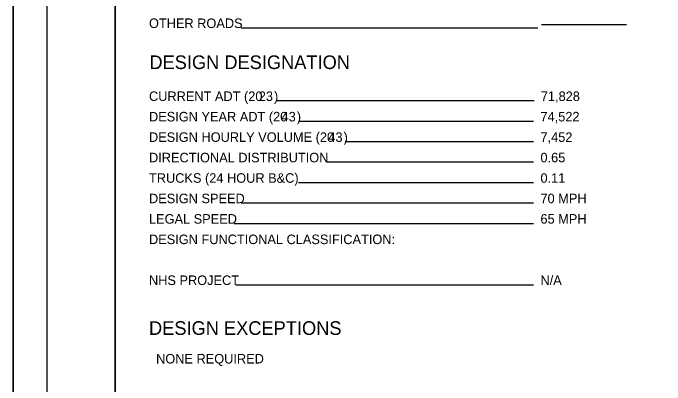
# Model space of a CAD drawing. Extents: x 0 to 44.3, y 0 to 22.
# Drawn here: x 0 to 9.56, y 5.64 to 11.1 of the extents above; entities that cross this region are included whole.
import ezdxf

# ---------------------------------------------------------------- set-up
doc = ezdxf.new("R2010")
doc.units = 0
for name, color, linetype in [('SH_Border', 7, 'Continuous'), ('SH_Cut_Line', 7, 'Continuous'), ('SH_Data', 7, 'Continuous'), ('SH_Text', 7, 'Continuous')]:
    doc.layers.add(name, color=color, linetype=linetype)

msp = doc.modelspace()

# ---------------------------------------------------------------- linework, layer by layer
at = {"layer": 'SH_Border'}
for points in [[(0.5, 21.5), (1.5, 21.5), (1.5, 0.5), (0.5, 0.5)], [(1.5, 21.5), (33.5, 21.5), (33.5, 0.5), (1.5, 0.5)]]:
    msp.add_lwpolyline(points, close=True, dxfattribs=at)
at = {"layer": 'SH_Cut_Line'}
for points in [[(0, 0), (34, 0), (34, 22), (0, 22)], [(0, 22), (34, 22), (34, 0), (0, 0)]]:
    msp.add_lwpolyline(points, close=True, dxfattribs=at)
at = {"layer": 'SH_Data'}
for p, q in [((9, 10.9223), (7.75, 10.9223)), ((7.7, 10.8767), (3.3471, 10.8767)), ((7.6424, 9.8062), (3.871, 9.8062)), ((7.6368, 9.5062), (4.1885, 9.5062)), ((7.6368, 9.2062), (4.8723, 9.2062)), ((7.6368, 8.9062), (4.6037, 8.9062)), ((7.6368, 8.6062), (4.1885, 8.6062)), ((7.6368, 8.3062), (3.346, 8.3062)), ((7.6368, 8.0062), (3.2422, 8.0062)), ((7.6368, 7.1062), (3.2669, 7.1062))]:
    msp.add_line(p, q, dxfattribs=at)

# ---------------------------------------------------------------- texts
msp.add_text('DESIGN DESIGNATION', height=0.2, dxfattribs=at).set_placement((2, 10.2747))
at = {"layer": 'SH_Text'}
for s, height, p in [('OTHER ROADS', 0.14, (1.9944, 10.8767)), ('CURRENT ADT (20', 0.14, (1.9944, 9.8062)), ('23', 0.14, (3.6047, 9.8062)), (')', 0.14, (3.8282, 9.8062)), ('71,828', 0.14, (7.7424, 9.8062)), ('DESIGN YEAR ADT (20', 0.14, (1.9944, 9.5062)), ('43', 0.14, (3.939, 9.5062)), (')', 0.14, (4.1625, 9.5062)), ('74,522', 0.14, (7.7368, 9.5062)), ('DESIGN HOURLY VOLUME (20', 0.14, (1.9944, 9.2062)), ('43', 0.14, (4.6254, 9.2062)), (')', 0.14, (4.8488, 9.2062)), ('7,452 ', 0.14, (7.7368, 9.2062)), ('DIRECTIONAL DISTRIBUTION', 0.14, (1.9944, 8.9062)), ('0.65  ', 0.14, (7.7368, 8.9062)), ('TRUCKS (24 HOUR B&C)', 0.14, (1.9944, 8.6062)), ('0.11  ', 0.14, (7.7368, 8.6062)), ('DESIGN SPEED', 0.14, (1.9944, 8.3062)), ('70 MPH', 0.14, (7.7368, 8.3062)), ('LEGAL SPEED', 0.14, (1.9944, 8.0062)), ('65 MPH', 0.14, (7.7368, 8.0062)), ('DESIGN FUNCTIONAL CLASSIFICATION:', 0.14, (1.9944, 7.7062)), ('NHS PROJECT', 0.14, (1.9944, 7.1062)), ('N/A   ', 0.14, (7.7368, 7.1062)), ('DESIGN EXCEPTIONS', 0.2, (1.9944, 6.3744)), ('  NONE REQUIRED                          ', 0.14, (1.9944, 5.9544))]:
    msp.add_text(s, height=height, dxfattribs=at).set_placement(p)

doc.saveas('drawing.dxf')
